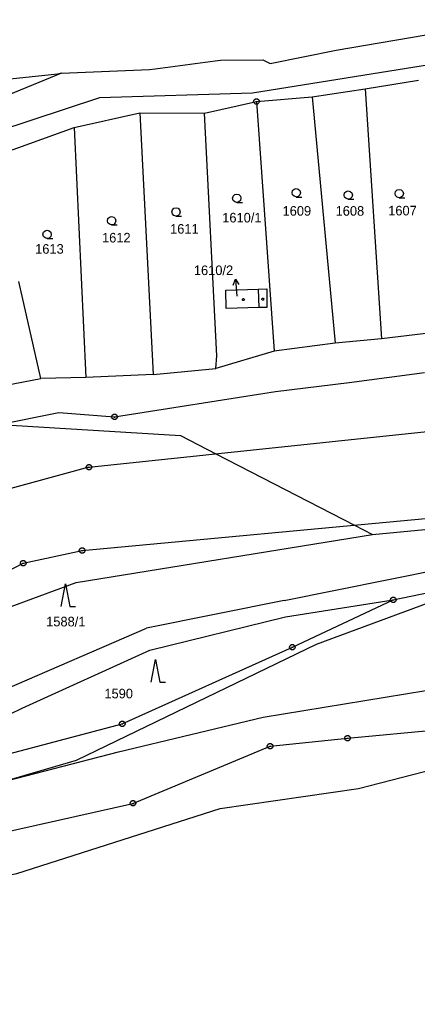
# Model space of a CAD drawing. Extents: x -806774 to -803680, y -1151731 to -1150053.
# Drawn here: x -806002.5 to -805932.1, y -1150704.3 to -1150530.4 of the extents above; entities that cross this region are included whole.
import ezdxf

# ---------------------------------------------------------------- set-up
doc = ezdxf.new("R2010")
doc.units = 0
for name, color, linetype in [('1', 7, 'Continuous'), ('11', 7, 'Continuous'), ('12', 7, 'Continuous'), ('2', 7, 'Continuous'), ('3', 7, 'Continuous'), ('4', 7, 'Continuous'), ('5', 7, 'Continuous'), ('6', 7, 'Continuous'), ('7', 7, 'Continuous'), ('8', 7, 'Continuous')]:
    doc.layers.add(name, color=color, linetype=linetype)

msp = doc.modelspace()

# ---------------------------------------------------------------- linework, layer by layer
at = {"layer": '1'}
for p, q in [((-805946.48, -1150535.78), (-805914.7, -1150530.39)), ((-805958.14, -1150538.16), (-805946.48, -1150535.78)), ((-805978.52, -1150539.1), (-805967.87, -1150537.65)), ((-805967.87, -1150537.65), (-805966.95, -1150537.56)), ((-805966.95, -1150537.56), (-805959.42, -1150537.5)), ((-805959.42, -1150537.5), (-805958.14, -1150538.16)), ((-805995.79, -1150540.03), (-806019.46, -1150542.59)), ((-805995.08, -1150539.89), (-805995.79, -1150540.03)), ((-805995.08, -1150539.89), (-805979.47, -1150539.21)), ((-805979.47, -1150539.21), (-805978.52, -1150539.1)), ((-805941.33, -1150542.63), (-805931.86, -1150541.09)), ((-805960.55, -1150544.86), (-805950.71, -1150544.04)), ((-805950.71, -1150544.04), (-805941.33, -1150542.63)), ((-805950.71, -1150544.04), (-805946.65, -1150587.64)), ((-805941.33, -1150542.63), (-805938.4, -1150586.88)), ((-805969.76, -1150546.96), (-805960.55, -1150544.86)), ((-805960.55, -1150544.86), (-805957.42, -1150589.07)), ((-805992.86, -1150549.46), (-805981.18, -1150546.9)), ((-805981.18, -1150546.9), (-805969.76, -1150546.96)), ((-805981.18, -1150546.9), (-805978.86, -1150593.2)), ((-805967.59, -1150589.89), (-805969.76, -1150546.96)), ((-806007.57, -1150554.77), (-805992.86, -1150549.46)), ((-805992.86, -1150549.46), (-805990.76, -1150593.74)), ((-805998.72, -1150593.9), (-806002.61, -1150576.71)), ((-805966.01, -1150578.24), (-805960.25, -1150578.09)), ((-805965.92, -1150581.52), (-805966.01, -1150578.24)), ((-805960.25, -1150578.09), (-805958.74, -1150578.04)), ((-805958.74, -1150578.04), (-805958.71, -1150581.32)), ((-805960.16, -1150581.36), (-805965.92, -1150581.52)), ((-805958.71, -1150581.32), (-805960.16, -1150581.36)), ((-805927.83, -1150585.59), (-805938.4, -1150586.88)), ((-805938.4, -1150586.88), (-805946.65, -1150587.64)), ((-805957.42, -1150589.07), (-805967.77, -1150592.14)), ((-805946.65, -1150587.64), (-805957.42, -1150589.07)), ((-805967.77, -1150592.14), (-805967.59, -1150589.89)), ((-805978.86, -1150593.2), (-805967.77, -1150592.14)), ((-806021.64, -1150598.35), (-805998.72, -1150593.9)), ((-805990.76, -1150593.74), (-805998.72, -1150593.9)), ((-805978.86, -1150593.2), (-805990.76, -1150593.74)), ((-805930.82, -1150592.93), (-805944.13, -1150594.65)), ((-805944.13, -1150594.65), (-805957.21, -1150596.28)), ((-805957.21, -1150596.28), (-805985.67, -1150600.72)), ((-805990.21, -1150609.59), (-805890.43, -1150599.04)), ((-805995.57, -1150599.97), (-806019.97, -1150604.84)), ((-805985.67, -1150600.72), (-805995.57, -1150599.97)), ((-805990.21, -1150609.59), (-806006.71, -1150614.09)), ((-805991.42, -1150624.34), (-805889.59, -1150614.88)), ((-805955.67, -1150633.22), (-805906.01, -1150623.2)), ((-806001.85, -1150626.61), (-805991.42, -1150624.34)), ((-806018.57, -1150635.19), (-806001.85, -1150626.61)), ((-805936.34, -1150633.1), (-805905.92, -1150626.68)), ((-805955.67, -1150633.22), (-805980.05, -1150638.11)), ((-805955.42, -1150636.11), (-805936.34, -1150633.1)), ((-805954.21, -1150641.47), (-805936.34, -1150633.1)), ((-805979.44, -1150641.98), (-805955.42, -1150636.11)), ((-806005.08, -1150648.95), (-805980.05, -1150638.11)), ((-806002.04, -1150652.23), (-805979.44, -1150641.98)), ((-805984.31, -1150655.05), (-805954.21, -1150641.47)), ((-806020.42, -1150661.14), (-806002.04, -1150652.23)), ((-806019.74, -1150664.32), (-805984.31, -1150655.05)), ((-805944.43, -1150657.58), (-805909.49, -1150654.26)), ((-805958.14, -1150658.97), (-805944.43, -1150657.58)), ((-805982.42, -1150669.1), (-805958.14, -1150658.97)), ((-806017.22, -1150676.88), (-805982.42, -1150669.1))]:
    msp.add_line(p, q, dxfattribs=at)
at = {"layer": '11'}
for points in [[(-806048.61, -1150602.81), (-806045.5, -1150603), (-806006.5, -1150602), (-806005.92, -1150602.04), (-805974, -1150604), (-805967.75, -1150607.22), (-805943.19, -1150619.86), (-805940, -1150621.5)], [(-805940, -1150621.5), (-805882.5, -1150616), (-805895.32, -1150620.75), (-805918.51, -1150629.34), (-805923, -1150631)], [(-806043.98, -1150675.01), (-806103, -1150686.5), (-806095.85, -1150682.49), (-806033.72, -1150647.64), (-806021, -1150640.5), (-805992.5, -1150630), (-805940, -1150621.5)], [(-805923, -1150631), (-805950, -1150641), (-805992.5, -1150661.5), (-806028.5, -1150672), (-806043.98, -1150675.01)], [(-806112.5, -1150711.88), (-806108.5, -1150706), (-806100, -1150704), (-806075.5, -1150701.5), (-806053.98, -1150694.05), (-806052.74, -1150693.62), (-806036.97, -1150688.16), (-806036.5, -1150688), (-806003, -1150681.5), (-805967, -1150670), (-805942.5, -1150666.5), (-805929, -1150663)]]:
    msp.add_lwpolyline(points, dxfattribs=at)
at = {"layer": '12'}
for p, q in [((-805958.14, -1150538.16), (-805946.48, -1150535.78)), ((-805959.42, -1150537.5), (-805958.14, -1150538.16)), ((-805966.01, -1150578.24), (-805960.25, -1150578.09)), ((-805965.92, -1150581.52), (-805966.01, -1150578.24)), ((-805960.25, -1150578.09), (-805960.16, -1150581.36)), ((-805960.16, -1150581.36), (-805965.92, -1150581.52))]:
    msp.add_line(p, q, dxfattribs=at)
at = {"layer": '3'}
for points in [[(-805964.04, -1150562.74), (-805964.42, -1150562.64), (-805964.69, -1150562.37), (-805964.79, -1150562), (-805964.69, -1150561.63), (-805964.42, -1150561.36), (-805964.05, -1150561.26), (-805963.68, -1150561.36), (-805963.41, -1150561.63), (-805963.31, -1150562.01), (-805963.41, -1150562.39), (-805963.68, -1150562.66), (-805964.06, -1150562.76), (-805963.06, -1150562.76)], [(-805953.52, -1150561.76), (-805953.9, -1150561.66), (-805954.17, -1150561.39), (-805954.27, -1150561.02), (-805954.17, -1150560.65), (-805953.9, -1150560.38), (-805953.53, -1150560.28), (-805953.16, -1150560.38), (-805952.89, -1150560.65), (-805952.79, -1150561.03), (-805952.89, -1150561.41), (-805953.16, -1150561.68), (-805953.54, -1150561.78), (-805952.54, -1150561.78)], [(-805944.31, -1150562.17), (-805944.69, -1150562.07), (-805944.96, -1150561.8), (-805945.06, -1150561.43), (-805944.96, -1150561.06), (-805944.69, -1150560.79), (-805944.32, -1150560.69), (-805943.95, -1150560.79), (-805943.68, -1150561.06), (-805943.58, -1150561.44), (-805943.68, -1150561.82), (-805943.95, -1150562.09), (-805944.33, -1150562.19), (-805943.33, -1150562.19)], [(-805935.28, -1150561.91), (-805935.66, -1150561.81), (-805935.93, -1150561.54), (-805936.03, -1150561.17), (-805935.93, -1150560.8), (-805935.66, -1150560.53), (-805935.29, -1150560.43), (-805934.92, -1150560.53), (-805934.65, -1150560.8), (-805934.55, -1150561.18), (-805934.65, -1150561.56), (-805934.92, -1150561.83), (-805935.3, -1150561.93), (-805934.3, -1150561.93)], [(-805974.79, -1150565.15), (-805975.17, -1150565.05), (-805975.44, -1150564.78), (-805975.54, -1150564.41), (-805975.44, -1150564.04), (-805975.17, -1150563.77), (-805974.8, -1150563.67), (-805974.43, -1150563.77), (-805974.16, -1150564.04), (-805974.06, -1150564.42), (-805974.16, -1150564.8), (-805974.43, -1150565.07), (-805974.81, -1150565.17), (-805973.81, -1150565.17)], [(-805986.2, -1150566.71), (-805986.58, -1150566.61), (-805986.85, -1150566.34), (-805986.95, -1150565.97), (-805986.85, -1150565.6), (-805986.58, -1150565.33), (-805986.21, -1150565.23), (-805985.84, -1150565.33), (-805985.57, -1150565.6), (-805985.47, -1150565.98), (-805985.57, -1150566.36), (-805985.84, -1150566.63), (-805986.22, -1150566.73), (-805985.22, -1150566.73)], [(-805997.61, -1150569.12), (-805997.99, -1150569.02), (-805998.26, -1150568.75), (-805998.36, -1150568.38), (-805998.26, -1150568.01), (-805997.99, -1150567.74), (-805997.62, -1150567.64), (-805997.25, -1150567.74), (-805996.98, -1150568.01), (-805996.88, -1150568.39), (-805996.98, -1150568.77), (-805997.25, -1150569.04), (-805997.63, -1150569.14), (-805996.63, -1150569.14)], [(-805995.12, -1150634.26), (-805994.37, -1150630.26), (-805993.62, -1150634.26), (-805992.62, -1150634.26)], [(-805979.19, -1150647.65), (-805978.44, -1150643.65), (-805977.69, -1150647.65), (-805976.69, -1150647.65)]]:
    msp.add_lwpolyline(points, dxfattribs=at)
at = {"layer": '4'}
for p, q in [((-805913.56, -1150535.79), (-805961.29, -1150543.38)), ((-805995.08, -1150539.89), (-806020.46, -1150550.22)), ((-805961.29, -1150543.38), (-805988.36, -1150544.24)), ((-805988.36, -1150544.24), (-806008.67, -1150550.93)), ((-805960.25, -1150578.09), (-805960.16, -1150581.36))]:
    msp.add_line(p, q, dxfattribs=at)
at = {"layer": '5'}
for points in [[(-805962.87, -1150579.76), (-805962.77, -1150579.78), (-805962.72, -1150579.87), (-805962.7, -1150579.93), (-805962.72, -1150580.02), (-805962.8, -1150580.09), (-805962.87, -1150580.1), (-805962.96, -1150580.07), (-805963.02, -1150580.01), (-805963.04, -1150579.93), (-805963.02, -1150579.84), (-805962.94, -1150579.77)], [(-805959.35, -1150579.71), (-805959.26, -1150579.86), (-805959.35, -1150580.01), (-805959.53, -1150580.01), (-805959.62, -1150579.86), (-805959.53, -1150579.71)]]:
    msp.add_lwpolyline(points, close=True, dxfattribs=at)
at = {"layer": '6'}
for p, q in [((-805959.35, -1150653.87), (-805930.55, -1150649.15)), ((-805984.98, -1150659.98), (-805959.35, -1150653.87)), ((-806072.82, -1150682.77), (-805984.98, -1150659.98))]:
    msp.add_line(p, q, dxfattribs=at)
at = {"layer": '7'}
msp.add_line((-805964.29, -1150576.34), (-805964.02, -1150579.33), dxfattribs=at)
msp.add_lwpolyline([(-805964.7, -1150577.38), (-805964.29, -1150576.34), (-805963.7, -1150577.29)], dxfattribs=at)
at = {"layer": '8'}
for p, q in [((-805960.67, -1150544.86), (-805960.43, -1150544.86)), ((-805985.79, -1150600.72), (-805985.55, -1150600.72)), ((-805990.33, -1150609.59), (-805990.09, -1150609.59)), ((-805991.54, -1150624.34), (-805991.3, -1150624.34)), ((-806001.97, -1150626.61), (-806001.73, -1150626.61)), ((-805936.46, -1150633.1), (-805936.22, -1150633.1)), ((-805954.33, -1150641.47), (-805954.09, -1150641.47)), ((-805984.43, -1150655.05), (-805984.19, -1150655.05)), ((-805944.55, -1150657.58), (-805944.31, -1150657.58)), ((-805958.26, -1150658.97), (-805958.02, -1150658.97)), ((-805982.54, -1150669.1), (-805982.3, -1150669.1))]:
    msp.add_line(p, q, dxfattribs=at)
for points in [[(-805960.4, -1150544.38), (-805960.15, -1150544.56), (-805960.05, -1150544.85), (-805960.15, -1150545.14), (-805960.4, -1150545.32), (-805960.71, -1150545.32), (-805960.96, -1150545.14), (-805961.06, -1150544.85), (-805960.96, -1150544.56), (-805960.71, -1150544.38)], [(-805985.52, -1150600.24), (-805985.27, -1150600.42), (-805985.17, -1150600.71), (-805985.27, -1150601), (-805985.52, -1150601.18), (-805985.83, -1150601.18), (-805986.08, -1150601), (-805986.18, -1150600.71), (-805986.08, -1150600.42), (-805985.83, -1150600.24)], [(-805990.06, -1150609.11), (-805989.81, -1150609.29), (-805989.71, -1150609.58), (-805989.81, -1150609.87), (-805990.06, -1150610.05), (-805990.37, -1150610.05), (-805990.62, -1150609.87), (-805990.72, -1150609.58), (-805990.62, -1150609.29), (-805990.37, -1150609.11)], [(-805991.27, -1150623.86), (-805991.02, -1150624.04), (-805990.92, -1150624.33), (-805991.02, -1150624.62), (-805991.27, -1150624.8), (-805991.58, -1150624.8), (-805991.83, -1150624.62), (-805991.93, -1150624.33), (-805991.83, -1150624.04), (-805991.58, -1150623.86)], [(-806001.7, -1150626.13), (-806001.45, -1150626.31), (-806001.35, -1150626.6), (-806001.45, -1150626.89), (-806001.7, -1150627.07), (-806002.01, -1150627.07), (-806002.26, -1150626.89), (-806002.36, -1150626.6), (-806002.26, -1150626.31), (-806002.01, -1150626.13)], [(-805936.19, -1150632.62), (-805935.94, -1150632.8), (-805935.84, -1150633.09), (-805935.94, -1150633.38), (-805936.19, -1150633.56), (-805936.5, -1150633.56), (-805936.75, -1150633.38), (-805936.85, -1150633.09), (-805936.75, -1150632.8), (-805936.5, -1150632.62)], [(-805954.06, -1150640.99), (-805953.81, -1150641.17), (-805953.71, -1150641.46), (-805953.81, -1150641.75), (-805954.06, -1150641.93), (-805954.37, -1150641.93), (-805954.62, -1150641.75), (-805954.72, -1150641.46), (-805954.62, -1150641.17), (-805954.37, -1150640.99)], [(-805984.16, -1150654.57), (-805983.91, -1150654.75), (-805983.81, -1150655.04), (-805983.91, -1150655.33), (-805984.16, -1150655.51), (-805984.47, -1150655.51), (-805984.72, -1150655.33), (-805984.82, -1150655.04), (-805984.72, -1150654.75), (-805984.47, -1150654.57)], [(-805944.28, -1150657.1), (-805944.03, -1150657.28), (-805943.93, -1150657.57), (-805944.03, -1150657.86), (-805944.28, -1150658.04), (-805944.59, -1150658.04), (-805944.84, -1150657.86), (-805944.94, -1150657.57), (-805944.84, -1150657.28), (-805944.59, -1150657.1)], [(-805957.99, -1150658.49), (-805957.74, -1150658.67), (-805957.64, -1150658.96), (-805957.74, -1150659.25), (-805957.99, -1150659.43), (-805958.3, -1150659.43), (-805958.55, -1150659.25), (-805958.65, -1150658.96), (-805958.55, -1150658.67), (-805958.3, -1150658.49)], [(-805982.27, -1150668.62), (-805982.02, -1150668.8), (-805981.92, -1150669.09), (-805982.02, -1150669.38), (-805982.27, -1150669.56), (-805982.58, -1150669.56), (-805982.83, -1150669.38), (-805982.93, -1150669.09), (-805982.83, -1150668.8), (-805982.58, -1150668.62)]]:
    msp.add_lwpolyline(points, close=True, dxfattribs=at)

# ---------------------------------------------------------------- texts
at = {"layer": '2'}
for s, height, p in [('1610/1', 1.7, (-805966.62, -1150566.29)), ('1609', 1.7, (-805955.94, -1150565.09)), ('1608', 1.7, (-805946.55, -1150565.09)), ('1607', 1.7, (-805937.24, -1150565.04)), ('1611', 1.7, (-805975.85, -1150568.27)), ('1612', 1.7, (-805987.9, -1150569.83)), ('1613', 1.7, (-805999.74, -1150571.82)), ('1610/2', 0.1, (-805964, -1150579.33)), ('1588/1', 1.7, (-805997.79, -1150637.78)), ('1590', 1.7, (-805987.48, -1150650.52))]:
    msp.add_text(s, height=height, dxfattribs=at).set_placement(p)
at = {"layer": '7'}
msp.add_text('1610/2', height=1.7, dxfattribs=at).set_placement((-805971.64, -1150575.6))

doc.saveas('drawing.dxf')
